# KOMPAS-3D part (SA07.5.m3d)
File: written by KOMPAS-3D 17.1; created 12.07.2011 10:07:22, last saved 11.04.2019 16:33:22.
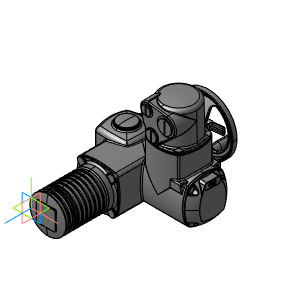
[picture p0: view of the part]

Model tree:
1. Плоскость XY
2. Плоскость ZX
3. Плоскость ZY
4. Ось X
5. Ось Y
6. Ось Z
7. Начало координат
8. Операция без истории:2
